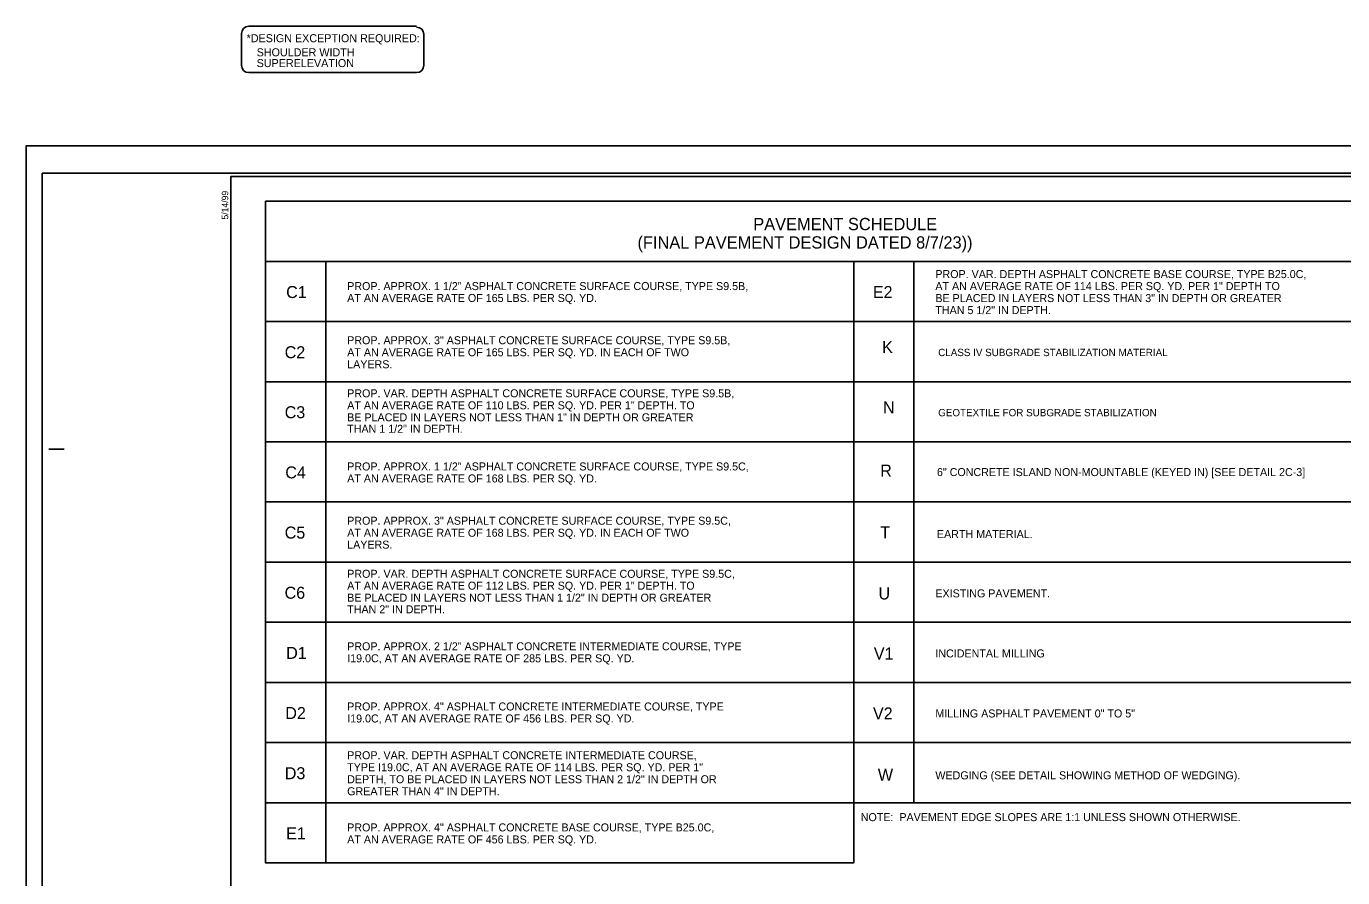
# Model space of a CAD drawing. Extents: x 1901718 to 1902220, y 193828 to 194187.
# Drawn here: x 1901965.8 to 1902073.3, y 194098.3 to 194167.8 of the extents above; entities that cross this region are included whole.
import ezdxf

# ---------------------------------------------------------------- set-up
doc = ezdxf.new("R2010")
doc.units = 0
for name, color, linetype in [('Old_Level_18', 7, 'Continuous'), ('Old_Level_19', 7, 'Continuous'), ('Old_Level_21', 7, 'Continuous'), ('Old_Level_38', 7, 'Continuous'), ('Prop Pavement Schedule Description CELL', 7, 'Continuous'), ('Sheet Border Standard 30in CELL', 7, 'Continuous'), ('Sheet Cutting Line CELL', 7, 'Continuous'), ('Sheet Plot Border Inside CELL', 7, 'Continuous'), ('Sheet Plot Border Outside CELL', 7, 'Continuous')]:
    doc.layers.add(name, color=color, linetype=linetype)

msp = doc.modelspace()

# ---------------------------------------------------------------- linework, layer by layer
at = {"layer": 'Old_Level_18'}
for p, q in [((1901984, 194167.76), (1901997.69, 194167.76)), ((1901983.4, 194167.16), (1901983.4, 194164.58)), ((1901998.29, 194167.16), (1901998.29, 194164.58)), ((1901984, 194163.98), (1901997.69, 194163.98))]:
    msp.add_line(p, q, dxfattribs=at)
for centre, start, end in [((1901984, 194167.16), 90, 180), ((1901997.69, 194167.09), 0, 90), ((1901984, 194164.58), 180, 270), ((1901997.69, 194164.58), 270, 0)]:
    msp.add_arc(centre, 0.6, start, end, dxfattribs=at)
at = {"layer": 'Old_Level_19'}
for points in [[(1901985.37, 194153.48), (1902081.37, 194153.48), (1902081.37, 194148.57), (1901985.37, 194148.57)], [(1901985.37, 194138.75), (1902033.37, 194138.75), (1902033.37, 194133.85), (1901985.37, 194133.85)]]:
    msp.add_lwpolyline(points, close=True, dxfattribs=at)
for points in [[(1901990.28, 194143.66), (1901985.37, 194143.66), (1901985.37, 194148.57), (1902033.37, 194148.57), (1902033.37, 194143.66), (1901990.28, 194143.66), (1901990.28, 194148.57)], [(1902038.28, 194143.66), (1902033.37, 194143.66), (1902033.37, 194148.57), (1902081.37, 194148.57), (1902081.37, 194143.66), (1902038.28, 194143.66), (1902038.28, 194148.57)], [(1901990.28, 194138.75), (1901985.37, 194138.75), (1901985.37, 194143.66), (1902033.37, 194143.66), (1902033.37, 194138.75), (1901990.28, 194138.75), (1901990.28, 194143.66)], [(1901990.28, 194133.85), (1901985.37, 194133.85), (1901985.37, 194138.75), (1902033.37, 194138.75), (1902033.37, 194133.85), (1901990.28, 194133.85), (1901990.28, 194138.75)], [(1901990.28, 194128.94), (1901985.37, 194128.94), (1901985.37, 194133.85), (1902033.37, 194133.85), (1902033.37, 194128.94), (1901990.28, 194128.94), (1901990.28, 194133.85)], [(1902038.28, 194128.94), (1902033.37, 194128.94), (1902033.37, 194133.85), (1902081.37, 194133.85), (1902081.37, 194128.94), (1902038.28, 194128.94), (1902038.28, 194133.85)], [(1901990.28, 194124.03), (1901985.37, 194124.03), (1901985.37, 194128.94), (1902033.37, 194128.94), (1902033.37, 194124.03), (1901990.28, 194124.03), (1901990.28, 194128.94)], [(1902038.28, 194124.03), (1902033.37, 194124.03), (1902033.37, 194128.94), (1902081.37, 194128.94), (1902081.37, 194124.03), (1902038.28, 194124.03), (1902038.28, 194128.94)], [(1901990.28, 194119.12), (1901985.37, 194119.12), (1901985.37, 194124.03), (1902033.37, 194124.03), (1902033.37, 194119.12), (1901990.28, 194119.12), (1901990.28, 194124.03)], [(1902038.28, 194119.12), (1902033.37, 194119.12), (1902033.37, 194124.03), (1902081.37, 194124.03), (1902081.37, 194119.12), (1902038.28, 194119.12), (1902038.28, 194124.03)], [(1901990.28, 194114.21), (1901985.37, 194114.21), (1901985.37, 194119.12), (1902033.37, 194119.12), (1902033.37, 194114.21), (1901990.28, 194114.21), (1901990.28, 194119.12)], [(1902038.28, 194114.21), (1902033.37, 194114.21), (1902033.37, 194119.12), (1902081.37, 194119.12), (1902081.37, 194114.21), (1902038.28, 194114.21), (1902038.28, 194119.12)], [(1901990.28, 194109.3), (1901985.37, 194109.3), (1901985.37, 194114.21), (1902033.37, 194114.21), (1902033.37, 194109.3), (1901990.28, 194109.3), (1901990.28, 194114.21)], [(1902038.28, 194109.3), (1902033.37, 194109.3), (1902033.37, 194114.21), (1902081.37, 194114.21), (1902081.37, 194109.3), (1902038.28, 194109.3), (1902038.28, 194114.21)], [(1901990.28, 194104.39), (1901985.37, 194104.39), (1901985.37, 194109.3), (1902033.37, 194109.3), (1902033.37, 194104.39), (1901990.28, 194104.39), (1901990.28, 194109.3)], [(1902038.28, 194104.39), (1902033.37, 194104.39), (1902033.37, 194109.3), (1902081.37, 194109.3), (1902081.37, 194104.39), (1902038.28, 194104.39), (1902038.28, 194109.3)], [(1901990.28, 194099.48), (1901985.37, 194099.48), (1901985.37, 194104.39), (1902033.37, 194104.39), (1902033.37, 194099.48), (1901990.28, 194099.48), (1901990.28, 194104.39)]]:
    msp.add_lwpolyline(points, dxfattribs=at)
at = {"layer": 'Prop Pavement Schedule Description CELL'}
for points in [[(1902038.28, 194138.75), (1902033.37, 194138.75), (1902033.37, 194143.66), (1902081.37, 194143.66), (1902081.37, 194138.75), (1902038.28, 194138.75), (1902038.28, 194143.66)], [(1902038.28, 194133.85), (1902033.37, 194133.85), (1902033.37, 194138.75), (1902081.37, 194138.75), (1902081.37, 194133.85), (1902038.28, 194133.85), (1902038.28, 194138.75)]]:
    msp.add_lwpolyline(points, dxfattribs=at)
at = {"layer": 'Sheet Border Standard 30in CELL'}
for p, q in [((1901982.64, 194155.51), (1901982.64, 194155.51)), ((1901967.69, 194133.26), (1901968.94, 194133.26))]:
    msp.add_line(p, q, dxfattribs=at)
msp.add_lwpolyline([(1902132.54, 194155.51), (1901982.54, 194155.51), (1901982.54, 194050.51), (1902132.54, 194050.51)], close=True, dxfattribs=at)
at = {"layer": 'Sheet Cutting Line CELL'}
for p, q in [((1902134.24, 194158.01), (1901965.84, 194158.01)), ((1901965.84, 194158.01), (1901965.84, 194048.01))]:
    msp.add_line(p, q, dxfattribs=at)
at = {"layer": 'Sheet Plot Border Inside CELL'}
msp.add_lwpolyline([(1902133.79, 194155.77), (1901967.14, 194155.77), (1901967.14, 194050.26), (1902133.79, 194050.26)], close=True, dxfattribs=at)
at = {"layer": 'Sheet Plot Border Outside CELL'}
msp.add_lwpolyline([(1902134.24, 194158.01), (1901965.84, 194158.01), (1901965.84, 194048.01), (1902134.24, 194048.01)], close=True, dxfattribs=at)

# ---------------------------------------------------------------- texts
at = {"layer": 'Old_Level_21'}
for s, height, p in [('PAVEMENT SCHEDULE ', 1, (1902025.17, 194151.12)), ('(FINAL PAVEMENT DESIGN DATED 8/7/23))', 1, (1902015.72, 194149.62)), ('PROP. VAR. DEPTH ASPHALT CONCRETE BASE COURSE, TYPE B25.0C,', 0.653, (1902040.03, 194147.21)), ('PROP. APPROX. 1 1/2" ASPHALT CONCRETE SURFACE COURSE, TYPE S9.5B,', 0.653, (1901992.03, 194146.23)), ('AT AN AVERAGE RATE OF 114 LBS. PER SQ. YD. PER 1" DEPTH TO', 0.653, (1902040.03, 194146.23)), ('C1', 0.98, (1901987.05, 194145.58)), ('AT AN AVERAGE RATE OF 165 LBS. PER SQ. YD.', 0.653, (1901992.03, 194145.26)), ('E2', 0.98, (1902034.93, 194145.58)), ('BE PLACED IN LAYERS NOT LESS THAN 3" IN DEPTH OR GREATER', 0.653, (1902040.03, 194145.25)), ('THAN 5 1/2" IN DEPTH.', 0.653, (1902040.03, 194144.27)), ('C2', 0.98, (1901986.93, 194140.67)), ('AT AN AVERAGE RATE OF 165 LBS. PER SQ. YD. IN EACH OF TWO', 0.653, (1901992.03, 194140.83)), ('PROP. APPROX. 3" ASPHALT CONCRETE SURFACE COURSE, TYPE S9.5B,', 0.653, (1901992.03, 194141.81)), ('LAYERS.', 0.653, (1901992.03, 194139.85)), ('AT AN AVERAGE RATE OF 110 LBS. PER SQ. YD. PER 1" DEPTH. TO', 0.653, (1901992.03, 194136.5)), ('PROP. VAR. DEPTH ASPHALT CONCRETE SURFACE COURSE, TYPE S9.5B,', 0.653, (1901992.03, 194137.48)), ('C3', 0.98, (1901986.93, 194135.77)), ('BE PLACED IN LAYERS NOT LESS THAN 1" IN DEPTH OR GREATER', 0.653, (1901992.03, 194135.52)), ('THAN 1 1/2" IN DEPTH.', 0.653, (1901992.03, 194134.58)), ('C4', 0.98, (1901986.98, 194130.86)), ('PROP. APPROX. 1 1/2" ASPHALT CONCRETE SURFACE COURSE, TYPE S9.5C,', 0.653, (1901992.03, 194131.51)), ('R', 0.98, (1902035.53, 194131.01)), ('AT AN AVERAGE RATE OF 168 LBS. PER SQ. YD.', 0.653, (1901992.03, 194130.53)), ('6" CONCRETE ISLAND NON-MOUNTABLE (KEYED IN) [SEE DETAIL 2C-3]', 0.653, (1902040.16, 194131.05)), ('PROP. APPROX. 3" ASPHALT CONCRETE SURFACE COURSE, TYPE S9.5C,', 0.653, (1901992.03, 194127.08)), ('C5', 0.98, (1901986.93, 194125.95)), ('AT AN AVERAGE RATE OF 168 LBS. PER SQ. YD. IN EACH OF TWO', 0.653, (1901992.03, 194126.1)), ('T', 0.98, (1902035.54, 194125.96)), ('EARTH MATERIAL.', 0.653, (1902040.16, 194125.99)), ('LAYERS.', 0.653, (1901992.03, 194125.13)), ('PROP. VAR. DEPTH ASPHALT CONCRETE SURFACE COURSE, TYPE S9.5C,', 0.653, (1901992.03, 194122.75)), ('AT AN AVERAGE RATE OF 112 LBS. PER SQ. YD. PER 1" DEPTH. TO', 0.653, (1901992.03, 194121.78)), ('C6', 0.98, (1901986.92, 194121.04)), ('BE PLACED IN LAYERS NOT LESS THAN 1 1/2" IN DEPTH OR GREATER', 0.653, (1901992.03, 194120.8)), ('U', 0.98, (1902035.39, 194120.98)), ('EXISTING PAVEMENT.', 0.653, (1902040.03, 194121.15)), ('THAN 2" IN DEPTH.', 0.653, (1901992.03, 194119.85)), ('D1', 0.98, (1901987.05, 194116.13)), ('PROP. APPROX. 2 1/2" ASPHALT CONCRETE INTERMEDIATE COURSE, TYPE', 0.653, (1901992.03, 194116.83)), ('V1', 0.98, (1902035.01, 194116.08)), ('INCIDENTAL MILLING', 0.653, (1902040.03, 194116.25)), ('I19.0C, AT AN AVERAGE RATE OF 285 LBS. PER SQ. YD.', 0.653, (1901992.03, 194115.85)), ('PROP. APPROX. 4" ASPHALT CONCRETE INTERMEDIATE COURSE, TYPE', 0.653, (1901992.03, 194111.92)), ('D2', 0.98, (1901986.98, 194111.22)), ('I19.0C, AT AN AVERAGE RATE OF 456 LBS. PER SQ. YD.', 0.653, (1901992.03, 194110.94)), ('V2', 0.98, (1902034.94, 194111.19)), ('MILLING ASPHALT PAVEMENT 0" TO 5"', 0.653, (1902040.03, 194111.35)), ('PROP. VAR. DEPTH ASPHALT CONCRETE INTERMEDIATE COURSE,', 0.653, (1901992.03, 194107.94)), ('D3', 0.98, (1901986.94, 194106.31)), ('TYPE I19.0C, AT AN AVERAGE RATE OF 114 LBS. PER SQ. YD. PER 1" ', 0.653, (1901992.03, 194106.96)), ('W', 0.98, (1902035.34, 194106.18)), ('DEPTH, TO BE PLACED IN LAYERS NOT LESS THAN 2 1/2" IN DEPTH OR', 0.653, (1901992.03, 194105.98)), ('WEDGING (SEE DETAIL SHOWING METHOD OF WEDGING).', 0.653, (1902040.03, 194106.3)), ('GREATER THAN 4" IN DEPTH.', 0.653, (1901992.03, 194105)), ('NOTE:  PAVEMENT EDGE SLOPES ARE 1:1 UNLESS SHOWN OTHERWISE.', 0.653, (1902033.94, 194102.89)), ('E1', 0.98, (1901987.05, 194101.4)), ('AT AN AVERAGE RATE OF 456 LBS. PER SQ. YD.', 0.653, (1901992.03, 194101.07)), ('PROP. APPROX. 4" ASPHALT CONCRETE BASE COURSE, TYPE B25.0C,', 0.653, (1901992.03, 194102.05))]:
    msp.add_text(s, height=height, dxfattribs=at).set_placement(p)
at = {"layer": 'Old_Level_38'}
for s, p in [('*DESIGN EXCEPTION REQUIRED: ', (1901983.82, 194166.46)), ('SHOULDER WIDTH', (1901984.64, 194165.31)), ('SUPERELEVATION', (1901984.64, 194164.43))]:
    msp.add_text(s, height=0.656, rotation=359.995, dxfattribs=at).set_placement(p)
at = {"layer": 'Prop Pavement Schedule Description CELL'}
for s, height, p in [('K', 0.98, (1902035.69, 194141.09)), ('CLASS IV SUBGRADE STABILIZATION MATERIAL', 0.6, (1902040.26, 194140.84)), ('N', 0.98, (1902035.75, 194136.18)), ('GEOTEXTILE FOR SUBGRADE STABILIZATION', 0.6, (1902040.26, 194135.93))]:
    msp.add_text(s, height=height, dxfattribs=at).set_placement(p)
at = {"layer": 'Sheet Border Standard 30in CELL'}
msp.add_text('5/14/99', height=0.525, rotation=90, dxfattribs=at).set_placement((1901982.32, 194151.99))

doc.saveas('drawing.dxf')
